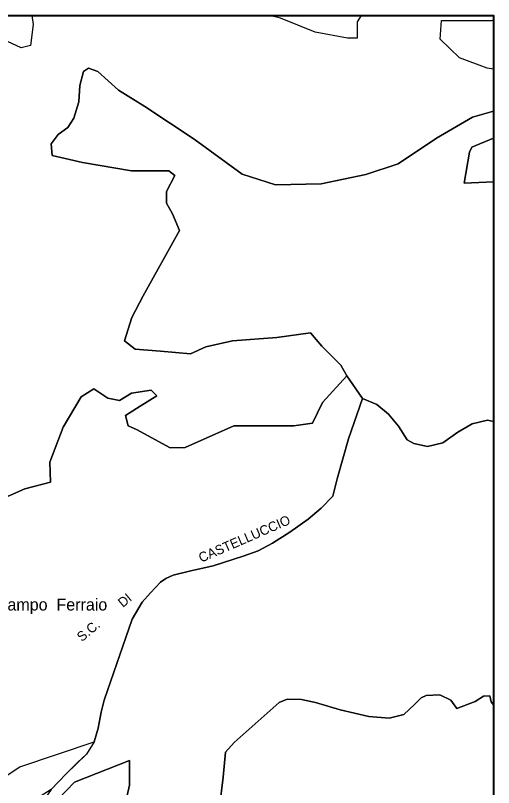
# Model space of a CAD drawing. Extents: x 650468 to 655025, y 889970 to 891591.
# Drawn here: x 654626 to 655025, y 890947 to 891591 of the extents above; entities that cross this region are included whole.
import ezdxf
from ezdxf.enums import TextEntityAlignment as Align

# ---------------------------------------------------------------- set-up
doc = ezdxf.new("R2010")
doc.units = 0
doc.header["$LTSCALE"] = 5.6
for name, color, linetype, lineweight in [('3', 7, 'Continuous', 25), ('35', 7, 'Continuous', 25), ('36', 7, 'Continuous', 25), ('37', 7, 'Continuous', 25), ('61', 7, 'Continuous', 35)]:
    doc.layers.add(name, color=color, linetype=linetype, lineweight=lineweight)
doc.layers.add('60', color=7, linetype='Continuous')

msp = doc.modelspace()

# ---------------------------------------------------------------- linework, layer by layer
at = {"layer": '3'}
msp.add_lwpolyline([(655000.69, 891451.15), (655025.2, 891452.22), (655025.2, 891488.61), (655007.07, 891481.17), (655005.07, 891477.01)], close=True, dxfattribs=at)
at = {"layer": '35'}
for points in [[(654630.14, 890964.31), (654692.09, 890985.03), (654695.39, 890996.67), (654698.09, 891009.76), (654700.41, 891020.02), (654708.51, 891043.29), (654718.4, 891072.09), (654723.8, 891087.51), (654732.2, 891101.76), (654739.1, 891109.33), (654747.49, 891118.35), (654751.99, 891121.26), (654757.99, 891124.16), (654772.68, 891127.66), (654791.27, 891131.95), (654816.52, 891139.95), (654828.9, 891144.45), (654840.75, 891150.95), (654855.19, 891159.95), (654870.65, 891170.95), (654881.47, 891179.95), (654891.27, 891189.95), (654894.88, 891204.45), (654904.16, 891237.96), (654916.01, 891271.46), (654902.72, 891290.5), (654882.68, 891268.14), (654874.16, 891250.97), (654858.63, 891248.7), (654818.55, 891248.7), (654808.53, 891248.7), (654767.89, 891230.71), (654755.64, 891230.46), (654727.36, 891245.78), (654720.35, 891248.7), (654718.34, 891257.44), (654730.37, 891265.22), (654744.39, 891273.74), (654739.64, 891278.49), (654723.35, 891275.91)], [(654723.35, 891275.91), (654713.14, 891269.98), (654703.64, 891271.74), (654691.89, 891279.49), (654681.27, 891273), (654666.24, 891247.72), (654655.21, 891218.56), (654655.63, 891201.68), (654634.17, 891196.2), (654610.12, 891185.51), (654585.63, 891178.66), (654565.03, 891184.54), (654558.94, 891138.75), (654604.36, 891088.17)], [(654614.69, 890954.07), (654630.14, 890964.31), (654692.09, 890985.03), (654685.79, 890974.85), (654668.7, 890958.56), (654656.4, 890945.47), (654631.8, 890929.74), (654613.87, 890916.44), (654587.96, 890904.47), (654561.39, 890894.84), (654542.79, 890888.85), (654523.19, 890882.21)], [(654560.8, 890966.6), (654570.67, 890966.6), (654583.91, 890964.06), (654595.44, 890960.94), (654604.46, 890955.58), (654614.69, 890954.07), (654630.14, 890964.31)]]:
    msp.add_lwpolyline(points, dxfattribs=at)
at = {"layer": '36'}
for points in [[(655025.2, 891587.42), (655025.2, 891591.08), (654914.78, 891591.08), (654911.55, 891585.86), (654911.55, 891572.25), (654903.53, 891572.25), (654876.47, 891577.11), (654847.41, 891588.78), (654838.22, 891591.08), (654640.2, 891591.08), (654641.16, 891583.42), (654639.16, 891565.93), (654631.32, 891564.12), (654616.29, 891570.92)], [(654757.42, 891425.62), (654752.41, 891434.36), (654752.41, 891444.09), (654759.43, 891457.69), (654754.42, 891461.58), (654723.35, 891461.58), (654682.27, 891468.39), (654657.22, 891474.22), (654656.22, 891483.94), (654662.23, 891491.72), (654670.24, 891497.55), (654675.26, 891505.33), (654679.26, 891518.94), (654680.27, 891532.55), (654683.27, 891544.21), (654687.28, 891547.13), (654695.3, 891544.21), (654712.33, 891528.66), (654734.38, 891515.05), (654775.46, 891487.83), (654815.54, 891458.67), (654843.41, 891449.77), (654881.48, 891450.74), (654918.56, 891458.52), (654945.62, 891467.27), (654977.68, 891488.65), (655007.74, 891506.15), (655025.2, 891511.17), (655025.2, 891546.32), (655019.77, 891546.98), (654996.72, 891555.73), (654980.69, 891571.28), (654981.69, 891586.83), (654997.72, 891586.83), (655023.78, 891586.83), (655025.2, 891587.42)], [(654610.12, 891185.51), (654634.17, 891196.2), (654655.63, 891201.68), (654655.21, 891218.56), (654666.24, 891247.72), (654681.27, 891273), (654691.89, 891279.49), (654703.64, 891271.74), (654713.14, 891269.98), (654723.35, 891275.91), (654739.64, 891278.49), (654744.39, 891273.74), (654730.37, 891265.22), (654718.34, 891257.44), (654720.35, 891248.7), (654727.36, 891245.78), (654755.64, 891230.46), (654767.89, 891230.71), (654808.53, 891248.7), (654818.55, 891248.7), (654858.63, 891248.7), (654874.16, 891250.97), (654882.68, 891268.14), (654902.72, 891290.5), (654897.71, 891299.24), (654881.91, 891315.26), (654872.66, 891326.46), (654844.6, 891322.57), (654807.53, 891319.66), (654785.17, 891314.51), (654772.42, 891308.75), (654747.4, 891310.91), (654726.42, 891312.76), (654717.42, 891319.76), (654723.67, 891339.02), (654732.98, 891357.23), (654763.27, 891411.8), (654757.42, 891425.62)], [(655016.95, 891023.33), (655022.1, 891023.4), (655023.31, 891018.58), (655025.2, 891015.9), (655025.2, 891252.46), (655020.14, 891253.46), (655007.25, 891250.46), (654995.4, 891243.46), (654983.02, 891234.46), (654970.14, 891231.46), (654958.8, 891233.96), (654953.13, 891236.96), (654945.91, 891248.46), (654937.66, 891258.46), (654927.87, 891266.46), (654916.01, 891271.46), (654904.16, 891237.96), (654894.88, 891204.45), (654891.27, 891189.95), (654881.47, 891179.95), (654870.65, 891170.95), (654855.19, 891159.95), (654840.75, 891150.95), (654828.9, 891144.45), (654816.52, 891139.95), (654791.27, 891131.95), (654772.68, 891127.66), (654757.99, 891124.16), (654751.99, 891121.26), (654747.49, 891118.35), (654739.1, 891109.33), (654732.2, 891101.76), (654723.8, 891087.51), (654718.4, 891072.09), (654708.51, 891043.29), (654700.41, 891020.02), (654698.09, 891009.76), (654695.39, 890996.67), (654692.09, 890985.03), (654685.79, 890974.85)], [(654846.38, 891017.87), (654853.08, 891020.87), (654864.93, 891020.37), (654876.79, 891017.87), (654897.41, 891011.87), (654921.12, 891006.37), (654938.13, 891004.87), (654950.5, 891007.87), (654959.27, 891016.37), (654964.94, 891021.87), (654969.06, 891023.87), (654980.4, 891024.37), (654989.68, 891019.87), (654994.52, 891012.82), (655009.73, 891018.83), (655016.95, 891023.33)], [(654685.79, 890974.85), (654678.29, 890967.87), (654668.7, 890958.56), (654656.4, 890945.47), (654645.3, 890929.76), (654638.71, 890919), (654635.71, 890912.89), (654634.86, 890908.35), (654647.96, 890922.47), (654675.69, 890951.44), (654721.52, 890969.55), (654721.52, 890949.03), (654709.46, 890894.71), (654734.78, 890903.16), (654755.28, 890914.02), (654794.86, 890907.77), (654796.64, 890930.61), (654799.73, 890955.61), (654801.79, 890976.62), (654809.01, 890984.62), (654846.38, 891017.87)]]:
    msp.add_lwpolyline(points, dxfattribs=at)
at = {"layer": '37'}
for points in [[(655025.2, 891452.22), (655000.69, 891451.15), (655005.07, 891477.01), (655007.07, 891481.17), (655025.2, 891488.61), (655025.2, 891511.17), (655007.74, 891506.15), (654977.68, 891488.65), (654945.62, 891467.27), (654918.56, 891458.52), (654881.48, 891450.74), (654843.41, 891449.77), (654815.54, 891458.67), (654775.46, 891487.83), (654734.38, 891515.05), (654712.33, 891528.66), (654695.3, 891544.21), (654687.28, 891547.13), (654683.27, 891544.21), (654680.27, 891532.55), (654679.26, 891518.94), (654675.26, 891505.33), (654670.24, 891497.55), (654662.23, 891491.72), (654656.22, 891483.94), (654657.22, 891474.22), (654682.27, 891468.39), (654723.35, 891461.58), (654754.42, 891461.58), (654759.43, 891457.69), (654752.41, 891444.09), (654752.41, 891434.36), (654757.42, 891425.62), (654763.27, 891411.8), (654732.98, 891357.23), (654723.67, 891339.02), (654717.42, 891319.76), (654726.42, 891312.76), (654747.4, 891310.91), (654772.42, 891308.75)], [(654772.42, 891308.75), (654785.17, 891314.51), (654807.53, 891319.66), (654844.6, 891322.57), (654872.66, 891326.46), (654881.91, 891315.26), (654897.71, 891299.24), (654902.72, 891290.5), (654916.01, 891271.46), (654927.87, 891266.46), (654937.66, 891258.46), (654945.91, 891248.46), (654953.13, 891236.96), (654958.8, 891233.96), (654970.14, 891231.46), (654983.02, 891234.46), (654995.4, 891243.46), (655007.25, 891250.46), (655020.14, 891253.46), (655025.2, 891252.46), (655025.2, 891452.22)], [(655025.2, 891015.9), (655023.31, 891018.58), (655022.1, 891023.4), (655016.95, 891023.33), (655009.73, 891018.83), (654994.52, 891012.82), (654989.68, 891019.87), (654980.4, 891024.37), (654969.06, 891023.87), (654964.94, 891021.87), (654959.27, 891016.37), (654950.5, 891007.87), (654938.13, 891004.87), (654921.12, 891006.37), (654897.41, 891011.87), (654876.79, 891017.87), (654864.93, 891020.37), (654853.08, 891020.87), (654846.38, 891017.87), (654809.01, 890984.62), (654801.79, 890976.62), (654799.73, 890955.61), (654796.64, 890930.61)], [(654990.35, 890837.32), (654999.43, 890851.46), (655008.52, 890863.58), (655006.5, 890873.68), (655002.46, 890883.77), (655010.54, 890894.88), (655025.2, 890903.97), (655025.2, 891015.9)], [(654709.46, 890894.71), (654721.52, 890949.03), (654721.52, 890969.55), (654675.69, 890951.44), (654647.96, 890922.47)]]:
    msp.add_lwpolyline(points, dxfattribs=at)
at = {"layer": '61', "lineweight": 40}
msp.add_lwpolyline([(653618.27, 891591.08), (655025.2, 891591.08), (655025.2, 889969.62), (653618.27, 889969.62)], close=True, dxfattribs=at)

# ---------------------------------------------------------------- texts
at = {"layer": '60'}
for s, rotation, p in [('CASTELLUCCIO', 23.497, (654818.98, 891150.89)), ('S.C.        DI', 39.809, (654703.08, 891085.95))]:
    msp.add_text(s, height=8, rotation=rotation, dxfattribs=at).set_placement(p, align=Align.CENTER)
msp.add_text('Campo  Ferraio', height=10, dxfattribs=at).set_placement((654656.6, 891094.69), align=Align.CENTER)

doc.saveas('drawing.dxf')
